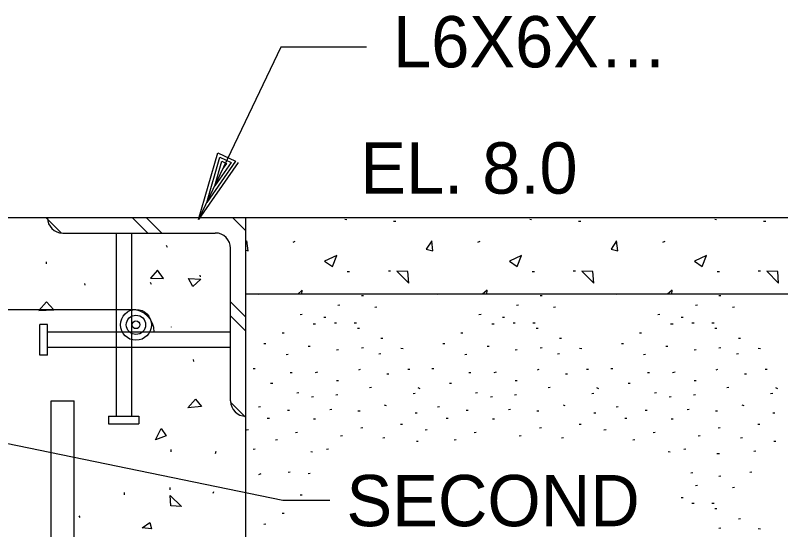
# Model space of a CAD drawing. Extents: x 0 to 320, y -4 to 473.
# Drawn here: x 32.485 to 34.575, y 15.822 to 17.226 of the extents above; entities that cross this region are included whole.
import ezdxf

# ---------------------------------------------------------------- set-up
doc = ezdxf.new("R2010")
doc.units = 0
for name, color, linetype in [('Level 10', 7, 'Continuous'), ('Level 2', 7, 'Continuous'), ('Level 3', 7, 'Continuous'), ('Level 44', 7, 'Continuous'), ('Level 50', 7, 'Continuous')]:
    doc.layers.add(name, color=color, linetype=linetype)

msp = doc.modelspace()

# ---------------------------------------------------------------- linework, layer by layer
at = {"layer": 'Level 10'}
for p, q in [((32.8999, 16.5926), (32.8976, 16.5975)), ((32.5695, 16.5478), (32.5699, 16.5529)), ((32.9899, 16.5126), (32.9895, 16.5171)), ((32.6754, 16.4893), (32.6746, 16.494)), ((32.8569, 16.4917), (32.8538, 16.4969)), ((32.9114, 16.375), (32.9115, 16.3755)), ((32.9724, 16.2809), (32.9714, 16.2869)), ((32.9099, 16.0348), (32.9099, 16.0411)), ((33.0311, 16.0298), (33.0329, 16.0361)), ((32.9077, 15.9312), (32.9077, 15.937)), ((33.0249, 15.922), (33.0267, 15.9265)), ((32.7824, 15.9177), (32.7824, 15.924)), ((32.6614, 15.8552), (32.6592, 15.8601))]:
    msp.add_line(p, q, dxfattribs=at)
for points in [[(32.8896, 16.5082), (32.8728, 16.5304), (32.854, 16.509)], [(32.9915, 16.5058), (32.9693, 16.486), (32.9574, 16.5082)], [(32.5899, 16.4227), (32.5701, 16.4441), (32.5489, 16.4204)], [(32.9558, 16.1545), (32.9764, 16.1783), (32.993, 16.1586)], [(32.8963, 16.0786), (32.8679, 16.0675), (32.8829, 16.0983)], [(32.9093, 15.8877), (32.9077, 15.9156), (32.9385, 15.8854)], [(32.8564, 15.8242), (32.8311, 15.8274), (32.8524, 15.8417)]]:
    msp.add_lwpolyline(points, close=True, dxfattribs=at)
at = {"layer": 'Level 2'}
for p, q in [((32.5724, 16.6736), (30.4995, 16.6736)), ((32.611, 16.6319), (32.5693, 16.6736)), ((33.1141, 16.6736), (32.5724, 16.6736)), ((32.8467, 16.6319), (32.805, 16.6736)), ((32.8844, 16.6319), (32.8427, 16.6736)), ((33.1141, 16.6379), (33.0784, 16.6736)), ((33.1141, 16.1319), (33.1141, 16.6736)), ((32.6141, 16.6319), (33.0308, 16.6319)), ((32.7599, 16.6319), (32.7599, 16.1319)), ((32.8016, 16.6319), (32.8016, 16.1319)), ((33.0724, 16.1736), (33.0724, 16.5903)), ((33.1141, 16.4022), (33.0724, 16.4439)), ((33.1141, 16.3645), (33.0724, 16.4062)), ((32.5516, 16.2986), (32.5516, 16.3819)), ((32.5724, 16.3819), (32.5516, 16.3819)), ((32.5724, 16.2986), (32.5724, 16.3819)), ((33.0724, 16.3611), (32.5724, 16.3611)), ((33.0724, 16.3194), (32.5724, 16.3194)), ((32.5724, 16.2986), (32.5516, 16.2986)), ((32.5828, 15.1736), (32.5828, 16.1736)), ((32.6453, 15.1736), (32.6453, 16.1736)), ((33.1141, 16.1288), (33.0724, 16.1705)), ((32.7391, 16.1319), (32.8224, 16.1319)), ((32.7391, 16.1319), (32.7391, 16.1111)), ((32.8224, 16.1319), (32.8224, 16.1111)), ((33.1141, 13.8403), (33.1141, 16.1319)), ((32.7391, 16.1111), (32.8224, 16.1111))]:
    msp.add_line(p, q, dxfattribs=at)
for centre, start, end in [((32.6141, 16.6736), 180, 270), ((33.0308, 16.5903), 0, 90), ((33.1141, 16.1736), 180, 270)]:
    msp.add_arc(centre, 0.0417, start, end, dxfattribs=at)
at = {"layer": 'Level 3'}
for p, q in [((36.431, 16.6736), (33.1141, 16.6736)), ((36.431, 16.4653), (33.1141, 16.4653)), ((33.1515, 16.4653), (33.1489, 16.4639)), ((33.4351, 16.4604), (33.4296, 16.4601)), ((33.6396, 16.4653), (33.6371, 16.4639)), ((33.9232, 16.4604), (33.9177, 16.4601)), ((34.1278, 16.4653), (34.1252, 16.4639)), ((34.4113, 16.4604), (34.4058, 16.4601)), ((33.3708, 16.4348), (33.3653, 16.4343)), ((33.4718, 16.4293), (33.4663, 16.4288)), ((33.8589, 16.4348), (33.8534, 16.4343)), ((33.9599, 16.4293), (33.9544, 16.4288)), ((34.3471, 16.4348), (34.3416, 16.4343)), ((34.4481, 16.4293), (34.4426, 16.4288)), ((23.4266, 16.4236), (32.8016, 16.4236)), ((33.2682, 16.4092), (33.2627, 16.4087)), ((33.7563, 16.4092), (33.7508, 16.4087)), ((34.2444, 16.4092), (34.2389, 16.4087)), ((33.3324, 16.4017), (33.3269, 16.4013)), ((33.3618, 16.3863), (33.3562, 16.3859)), ((33.4163, 16.3863), (33.4101, 16.3863)), ((33.8206, 16.4017), (33.8151, 16.4013)), ((33.8499, 16.3863), (33.8443, 16.3859)), ((33.9044, 16.3863), (33.8982, 16.3863)), ((34.3087, 16.4017), (34.3032, 16.4013)), ((34.3381, 16.3863), (34.3324, 16.3859)), ((34.3926, 16.3863), (34.3863, 16.3863)), ((33.3044, 16.3836), (33.2977, 16.3836)), ((33.4241, 16.3717), (33.4186, 16.3713)), ((33.7926, 16.3836), (33.7858, 16.3836)), ((33.9122, 16.3717), (33.9067, 16.3713)), ((34.2807, 16.3836), (34.2739, 16.3836)), ((34.4003, 16.3717), (34.3948, 16.3713)), ((33.2187, 16.3589), (33.2132, 16.3584)), ((33.4883, 16.3442), (33.4828, 16.3437)), ((33.7068, 16.3589), (33.7013, 16.3584)), ((33.9764, 16.3442), (33.9709, 16.3437)), ((34.1949, 16.3589), (34.1894, 16.3584)), ((34.4646, 16.3442), (34.4591, 16.3437)), ((33.1691, 16.3296), (33.1636, 16.3291)), ((33.6572, 16.3296), (33.6517, 16.3291)), ((34.1453, 16.3296), (34.1398, 16.3291)), ((33.2902, 16.3222), (33.2847, 16.3218)), ((33.3673, 16.3131), (33.3618, 16.3126)), ((33.4351, 16.3186), (33.4296, 16.3181)), ((33.4828, 16.3019), (33.4773, 16.3016)), ((33.5437, 16.3161), (33.5372, 16.3171)), ((33.7783, 16.3222), (33.7728, 16.3218)), ((33.8554, 16.3131), (33.8499, 16.3126)), ((33.9232, 16.3186), (33.9177, 16.3181)), ((33.9709, 16.3019), (33.9654, 16.3016)), ((34.0318, 16.3161), (34.0253, 16.3171)), ((34.2664, 16.3222), (34.2609, 16.3218)), ((34.3436, 16.3131), (34.3381, 16.3126)), ((34.4113, 16.3186), (34.4058, 16.3181)), ((34.4591, 16.3019), (34.4536, 16.3016)), ((34.5199, 16.3161), (34.5134, 16.3171)), ((33.2296, 16.3002), (33.2241, 16.2997)), ((33.7177, 16.3002), (33.7122, 16.2997)), ((34.2058, 16.3002), (34.2003, 16.2997)), ((33.1397, 16.2616), (33.1342, 16.2612)), ((33.5617, 16.2598), (33.5562, 16.2593)), ((33.6278, 16.2616), (33.6223, 16.2612)), ((34.0498, 16.2598), (34.0443, 16.2593)), ((34.1159, 16.2616), (34.1104, 16.2612)), ((34.5379, 16.2598), (34.5324, 16.2593)), ((33.2406, 16.2507), (33.2351, 16.2502)), ((33.3098, 16.2526), (33.3031, 16.2507)), ((33.4262, 16.2593), (33.4214, 16.2574)), ((33.5048, 16.2469), (33.4993, 16.2466)), ((33.7287, 16.2507), (33.7232, 16.2502)), ((33.7979, 16.2526), (33.7912, 16.2507)), ((33.9143, 16.2593), (33.9096, 16.2574)), ((33.9929, 16.2469), (33.9874, 16.2466)), ((34.2168, 16.2507), (34.2113, 16.2502)), ((34.2861, 16.2526), (34.2793, 16.2507)), ((34.4024, 16.2593), (34.3977, 16.2574)), ((34.4811, 16.2469), (34.4756, 16.2466)), ((33.1874, 16.2213), (33.1818, 16.2209)), ((33.3673, 16.2287), (33.3618, 16.2282)), ((33.6756, 16.2213), (33.6699, 16.2209)), ((33.8554, 16.2287), (33.8499, 16.2282)), ((34.1637, 16.2213), (34.1581, 16.2209)), ((34.3436, 16.2287), (34.3381, 16.2282)), ((33.4572, 16.2103), (33.4517, 16.2098)), ((33.5903, 16.2063), (33.5847, 16.2097)), ((33.9453, 16.2103), (33.9398, 16.2098)), ((34.0784, 16.2063), (34.0728, 16.2097)), ((34.4334, 16.2103), (34.4279, 16.2098)), ((34.5666, 16.2063), (34.5609, 16.2097)), ((33.2589, 16.1956), (33.2534, 16.1951)), ((33.2993, 16.1847), (33.2938, 16.1842)), ((33.3653, 16.1901), (33.3598, 16.1896)), ((33.5764, 16.1938), (33.5709, 16.1933)), ((33.7471, 16.1956), (33.7416, 16.1951)), ((33.7874, 16.1847), (33.7819, 16.1842)), ((33.8534, 16.1901), (33.8479, 16.1896)), ((34.0646, 16.1938), (34.0591, 16.1933)), ((34.2352, 16.1956), (34.2297, 16.1951)), ((34.2756, 16.1847), (34.2701, 16.1842)), ((34.3416, 16.1901), (34.3361, 16.1896)), ((34.5527, 16.1938), (34.5472, 16.1933)), ((33.1544, 16.1571), (33.1489, 16.1567)), ((33.4983, 16.1599), (33.4931, 16.1624)), ((33.6426, 16.1571), (33.6371, 16.1567)), ((33.9864, 16.1599), (33.9812, 16.1624)), ((34.1307, 16.1571), (34.1252, 16.1567)), ((34.4746, 16.1599), (34.4693, 16.1624)), ((33.2333, 16.1478), (33.2278, 16.1474)), ((33.3488, 16.1498), (33.3433, 16.1493)), ((33.4259, 16.1461), (33.4203, 16.1456)), ((33.5819, 16.1406), (33.5764, 16.1401)), ((33.7214, 16.1478), (33.7159, 16.1474)), ((33.8369, 16.1498), (33.8314, 16.1493)), ((33.9141, 16.1461), (33.9084, 16.1456)), ((34.0701, 16.1406), (34.0646, 16.1401)), ((34.2096, 16.1478), (34.2041, 16.1474)), ((34.3251, 16.1498), (34.3196, 16.1493)), ((34.4022, 16.1461), (34.3966, 16.1456)), ((34.5582, 16.1406), (34.5527, 16.1401)), ((33.1783, 16.1259), (33.1728, 16.1254)), ((33.3048, 16.1241), (33.2993, 16.1236)), ((33.6664, 16.1259), (33.6609, 16.1254)), ((33.7929, 16.1241), (33.7874, 16.1236)), ((34.1546, 16.1259), (34.1491, 16.1254)), ((34.2811, 16.1241), (34.2756, 16.1236)), ((33.1213, 16.0947), (33.1158, 16.0942)), ((33.4333, 16.1002), (33.4278, 16.0997)), ((33.5416, 16.1094), (33.5361, 16.1089)), ((33.6094, 16.0947), (33.6039, 16.0942)), ((33.9214, 16.1002), (33.9159, 16.0997)), ((34.0297, 16.1094), (34.0242, 16.1089)), ((34.0976, 16.0947), (34.0921, 16.0942)), ((34.4096, 16.1002), (34.4041, 16.0997)), ((34.5178, 16.1094), (34.5123, 16.1089)), ((33.2553, 16.0873), (33.2498, 16.0869)), ((33.3782, 16.0782), (33.3727, 16.0778)), ((33.4938, 16.0727), (33.4883, 16.0723)), ((33.7434, 16.0873), (33.7379, 16.0869)), ((33.8663, 16.0782), (33.8608, 16.0778)), ((33.9819, 16.0727), (33.9764, 16.0723)), ((34.2316, 16.0873), (34.2261, 16.0869)), ((34.3544, 16.0782), (34.3489, 16.0778)), ((34.4701, 16.0727), (34.4646, 16.0723)), ((33.2003, 16.0672), (33.1948, 16.0668)), ((33.5847, 16.0627), (33.5798, 16.0632)), ((33.6884, 16.0672), (33.6829, 16.0668)), ((34.1766, 16.0672), (34.1711, 16.0668)), ((34.5609, 16.0627), (34.5561, 16.0632)), ((33.1397, 16.0416), (33.1342, 16.0411)), ((33.2964, 16.0334), (33.2913, 16.0343)), ((33.3397, 16.0416), (33.3342, 16.0411)), ((34.2727, 16.0334), (34.2676, 16.0343)), ((34.3159, 16.0416), (34.3104, 16.0411)), ((34.5068, 16.0361), (34.5012, 16.0356)), ((34.4071, 16.0293), (34.4003, 16.0293)), ((33.1548, 15.9746), (33.1489, 15.9716)), ((33.2351, 15.9791), (33.2296, 15.9787)), ((33.2902, 15.9754), (33.2847, 15.9749)), ((34.3343, 15.9773), (34.3288, 15.9768)), ((34.4113, 15.9681), (34.4058, 15.9677)), ((34.4957, 15.9791), (34.4902, 15.9787)), ((34.3471, 15.9424), (34.3416, 15.9419)), ((34.4481, 15.9369), (34.4426, 15.9364)), ((33.2682, 15.9168), (33.2627, 15.9163)), ((34.3087, 15.9093), (34.3032, 15.9089)), ((34.3381, 15.8939), (34.3324, 15.8936)), ((34.3926, 15.8939), (34.3863, 15.8939)), ((33.2187, 15.8666), (33.2132, 15.8661)), ((34.4003, 15.8793), (34.3948, 15.8789)), ((34.4646, 15.8518), (34.4591, 15.8513)), ((33.1691, 15.8372), (33.1636, 15.8367)), ((34.4113, 15.8262), (34.4058, 15.8257)), ((34.5199, 15.8237), (34.5134, 15.8247))]:
    msp.add_line(p, q, dxfattribs=at)
for points in [[(33.4432, 17.1394), (33.2094, 17.1394), (32.9853, 16.6687)], [(33.3434, 15.9016), (33.2155, 15.9016), (32.0969, 16.1319)]]:
    msp.add_lwpolyline(points, dxfattribs=at)
msp.add_arc((32.8016, 16.3611), 0.0625, 0, 90, dxfattribs=at)
at = {"layer": 'Level 44'}
for p, q in [((33.3896, 16.6676), (33.3846, 16.6685)), ((33.5241, 16.6633), (33.5174, 16.6633)), ((33.8946, 16.6676), (33.8896, 16.6685)), ((34.0291, 16.6633), (34.0224, 16.6633)), ((34.3996, 16.6676), (34.3946, 16.6685)), ((34.5341, 16.6633), (34.5274, 16.6633)), ((33.2481, 16.6087), (33.2421, 16.6057)), ((33.7531, 16.6087), (33.7471, 16.6057)), ((34.2581, 16.6087), (34.2521, 16.6057)), ((33.3976, 16.5257), (33.3909, 16.5257)), ((33.5096, 16.5281), (33.5033, 16.5281)), ((33.9026, 16.5257), (33.8959, 16.5257)), ((34.0146, 16.5281), (34.0083, 16.5281)), ((34.4076, 16.5257), (34.4009, 16.5257)), ((34.5196, 16.5281), (34.5133, 16.5281)), ((32.5828, 16.1736), (32.6453, 16.1736))]:
    msp.add_line(p, q, dxfattribs=at)
for points in [[(33.1141, 16.5848), (33.1201, 16.5833), (33.1166, 16.6107), (33.1141, 16.6069)], [(33.2672, 16.4653), (33.2684, 16.4762), (33.2558, 16.4653)], [(33.7722, 16.4653), (33.7734, 16.4762), (33.7608, 16.4653)], [(34.2772, 16.4653), (34.2784, 16.4762), (34.2658, 16.4653)]]:
    msp.add_lwpolyline(points, dxfattribs=at)
for points in [[(33.6251, 16.5833), (33.6216, 16.6107), (33.6063, 16.5878)], [(34.1301, 16.5833), (34.1266, 16.6107), (34.1113, 16.5878)], [(33.3504, 16.5403), (33.3623, 16.571), (33.3291, 16.5548)], [(33.8554, 16.5403), (33.8673, 16.571), (33.8341, 16.5548)], [(34.3604, 16.5403), (34.3723, 16.571), (34.3391, 16.5548)], [(33.5565, 16.5265), (33.5265, 16.5281), (33.559, 16.4948)], [(34.0615, 16.5265), (34.0315, 16.5281), (34.064, 16.4948)], [(34.5665, 16.5265), (34.5365, 16.5281), (34.569, 16.4948)]]:
    msp.add_lwpolyline(points, close=True, dxfattribs=at)
at = {"layer": 'Level 50'}
for p, q in [((33.0076, 16.7156), (33.0076, 16.7156)), ((32.9853, 16.6687), (32.9853, 16.6687))]:
    msp.add_line(p, q, dxfattribs=at)
msp.add_lwpolyline([(33.0936, 16.8242), (32.9853, 16.6687), (33.0377, 16.8509), (33.0855, 16.8281), (33.0076, 16.7156), (33.0433, 16.8393), (33.0739, 16.8247), (33.0291, 16.7608), (33.0488, 16.8278), (33.0615, 16.8218), (33.0515, 16.8078)], dxfattribs=at)
for radius in [0.0422, 0.0264, 0.0105]:
    msp.add_circle((32.8142, 16.3814), radius, dxfattribs=at)

# ---------------------------------------------------------------- texts
at = {"layer": 'Level 3'}
for s, p in [('L6X6X…', (33.5162, 17.0841)), ('EL. 8.0', (33.4268, 16.7394)), ('SECOND', (33.3888, 15.8316))]:
    msp.add_text(s, height=0.14, dxfattribs=at).set_placement(p)

doc.saveas('drawing.dxf')
